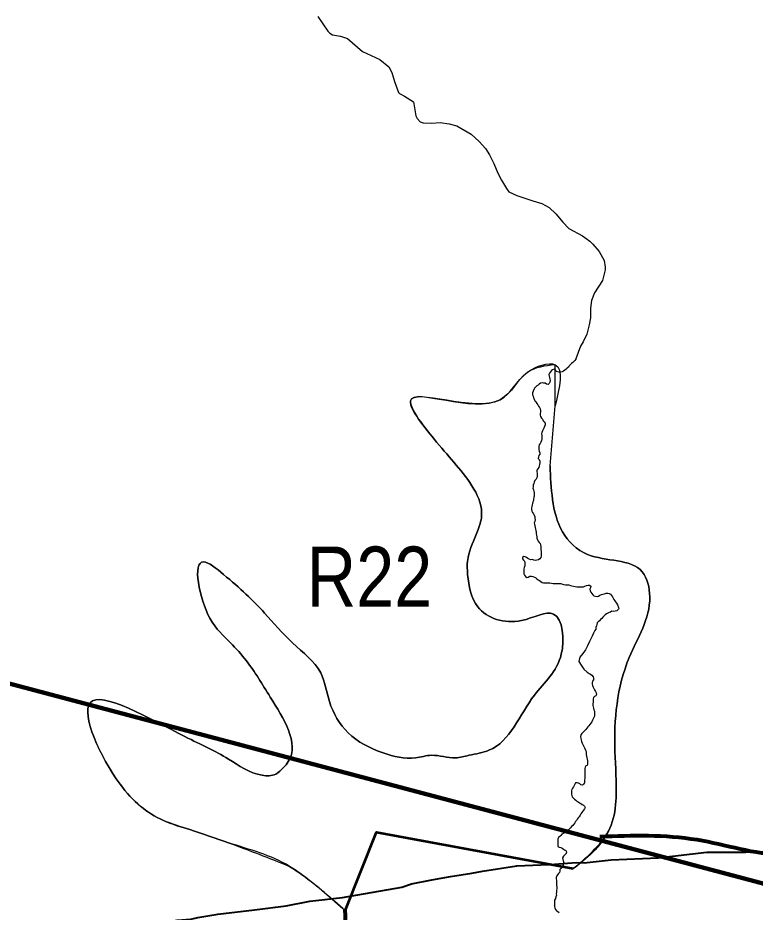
# Model space of a CAD drawing. Extents: x 553962 to 842807, y 8883888 to 9032388.
# Drawn here: x 729677 to 735808, y 8960680 to 8968113 of the extents above; entities that cross this region are included whole.
import ezdxf
from ezdxf.enums import TextEntityAlignment as Align

# ---------------------------------------------------------------- set-up
doc = ezdxf.new("R2010")
doc.units = 0
doc.header["$LTSCALE"] = 200
for name, color, linetype, lineweight in [('12', 7, 'Continuous', 25), ('24', 7, 'Continuous', 25), ('50', 7, 'Continuous', 80), ('51', 7, 'Continuous', 25), ('9', 7, 'Continuous', 90)]:
    doc.layers.add(name, color=color, linetype=linetype, lineweight=lineweight)
doc.layers.add('53', color=7, linetype='Continuous')

msp = doc.modelspace()

# ---------------------------------------------------------------- linework, layer by layer
at = {"layer": '12', "lineweight": 40}
for points in [[(735620.8, 8961178.7), (735731.5, 8961178.7), (735939.1, 8961184.7), (736086.4, 8961182.8), (736197.1, 8961189.1), (736304, 8961187.6), (736462.5, 8961200.2), (736543.4, 8961202.1), (736665.1, 8961195.8), (736768.2, 8961197.3), (737022.4, 8961176.7), (737121.8, 8961176.5), (737224.9, 8961184.4), (737328.1, 8961184.8), (737486.6, 8961197.6), (738285.5, 8961221)], [(734025.2, 8961072.3), (734102.4, 8961075.4), (734319.4, 8961091.8), (734386.9, 8961089), (734610.5, 8961116.1), (735000.8, 8961131.4), (735406.2, 8961178.8), (735620.8, 8961178.7)], [(733119.6, 8960947.4), (733273.3, 8960975.6), (733450.7, 8961003.1), (733541.8, 8961022), (733827, 8961064.4), (734025.2, 8961072.3)], [(731644.2, 8960700.6), (731907.1, 8960733.7), (732104.6, 8960770.6), (732375, 8960800.8), (732870.2, 8960888.2), (732949.7, 8960916.3), (733119.6, 8960947.4)], [(727488.2, 8960282.3), (728636.4, 8960199.6), (728903.4, 8960161.8), (729137.1, 8960189.3), (729219.7, 8960208.1), (729401, 8960258.8), (729465.4, 8960280.4), (729590.6, 8960330), (729719.4, 8960363), (729852.5, 8960406), (729969, 8960418.2), (730064.3, 8960434.8), (730362.8, 8960475.9), (730505.9, 8960510.9), (731000.5, 8960614.4), (731116.1, 8960622.6), (731172.1, 8960636.4), (731339.7, 8960662.3), (731644.2, 8960700.6)]]:
    msp.add_lwpolyline(points, dxfattribs=at)
at = {"layer": '24'}
for points in [[(732172.3, 8968124.3), (732254.1, 8968003.8), (732270.8, 8967986), (732292.3, 8967973.5), (732359.4, 8967962.3), (732419.1, 8967940.3), (732541.4, 8967832.4), (732686.6, 8967768.5), (732762.4, 8967705.5), (732787.2, 8967659.9), (732807.8, 8967584.8), (732842.4, 8967493.1), (732851.1, 8967484), (732892.3, 8967462.8), (732967.3, 8967414.9), (732986, 8967300), (732997.8, 8967278.1), (733022.8, 8967248.5), (733047.5, 8967241.4), (733120.3, 8967238.6), (733188.8, 8967243.5), (733264.7, 8967233.7), (733328, 8967214.7), (733447.7, 8967146.1), (733512.9, 8967086.8), (733564.5, 8967027.4), (733599.2, 8966975.3), (733599.2, 8966975.3), (733635.8, 8966903.5)], [(733635.8, 8966903.5), (733667.4, 8966823.6), (733697.2, 8966763.3), (733739, 8966694.9), (733760.7, 8966668.4), (733825.8, 8966637.8), (733959, 8966591.6), (734034.5, 8966569.7), (734094.6, 8966536.2), (734151.5, 8966485), (734209.2, 8966415.7), (734259.6, 8966363.7), (734370.9, 8966301.9), (734433.4, 8966256), (734458.6, 8966232.5), (734511.2, 8966171.1), (734552, 8966096.3), (734560.3, 8966041.1), (734559.6, 8966020.2), (734537.3, 8965930.7), (734471.1, 8965828), (734446.2, 8965764.4), (734439.5, 8965701), (734438, 8965620.3), (734427.4, 8965560.6), (734408.2, 8965484.4), (734379, 8965420.6), (734356.7, 8965384.2), (734317.4, 8965278.9)], [(734317.4, 8965278.9), (734316.7, 8965277.6), (734309.6, 8965266), (734300.3, 8965256.2), (734290.8, 8965248), (734280, 8965241.5), (734271, 8965232.4), (734262.1, 8965222.2), (734255.2, 8965210.8), (734246, 8965201.4), (734235.3, 8965192.4), (734225.2, 8965183.6), (734214.5, 8965176.8), (734203.3, 8965171.2), (734191.1, 8965169), (734176.5, 8965168.2), (734165.4, 8965170.5), (734153.3, 8965175.2), (734146.5, 8965187.1), (734135.5, 8965193.7), (734123.7, 8965189.1), (734113.9, 8965181), (734104.7, 8965171.5), (734096.9, 8965160.2), (734092, 8965148.5), (734093.8, 8965135.7), (734099.1, 8965124.2), (734101.8, 8965111.2), (734104.4, 8965098.9), (734101.7, 8965086.3), (734094.8, 8965075.1), (734085.3, 8965066.8), (734072.7, 8965069.6), (734061.6, 8965075.9), (734048.7, 8965077.6), (734035.9, 8965079.3), (734022.6, 8965077.8), (734012.9, 8965069.3), (734002.3, 8965061.6), (733992.1, 8965054.2), (733982.6, 8965044.5), (733973.5, 8965035.4), (733966.4, 8965023.8), (733961.2, 8965011.2), (733957.4, 8964996.8), (733956.8, 8964980.1), (733961.7, 8964967.6), (733965, 8964954.8), (733969.4, 8964942.7), (733975.5, 8964931.1), (733983, 8964920.4), (733992.3, 8964907.2), (733999.9, 8964896), (734007, 8964885.5), (734014.1, 8964874.7), (734019.1, 8964863.1), (734023, 8964850.6), (734021.8, 8964836.9), (734020.6, 8964824.1), (734020.5, 8964810.9), (734024.2, 8964798.7), (734031.2, 8964786.5), (734039.1, 8964776.3), (734045.8, 8964764.7), (734054.2, 8964754.9)], [(734054.2, 8964754.9), (734060.9, 8964743.3), (734062.1, 8964730.9), (734057.1, 8964716.4), (734051.1, 8964704.2), (734044.2, 8964692), (734039, 8964679.5), (734033.5, 8964667.7), (734031.7, 8964654.4), (734034.2, 8964641.1), (734034.2, 8964628.3), (734034.1, 8964613), (734031.7, 8964599), (734024.3, 8964586.6), (734018.8, 8964574.7), (734012.7, 8964563), (734010, 8964550.6), (734009.5, 8964537.9), (734009, 8964524.6), (734010.7, 8964510.9), (734016.3, 8964498.6), (734016.6, 8964486), (734010.2, 8964474.6), (734005, 8964463.3), (734003.8, 8964450.7), (734012.6, 8964441.7), (734016, 8964428.6), (734016.2, 8964415.1), (734015.3, 8964401.5), (734012.5, 8964389.2), (734008.2, 8964375), (733999.7, 8964365), (733992.6, 8964354.2), (733992.8, 8964341.2), (733995.2, 8964328.2), (733996.5, 8964315.3), (733996.1, 8964302.6)], [(733996.1, 8964302.6), (733991.3, 8964290.8), (733985.7, 8964278.4), (733977, 8964266.7), (733970.8, 8964254.3), (733966.8, 8964241.9), (733962.8, 8964229.6), (733960.8, 8964216.6), (733959.5, 8964204), (733963.7, 8964190.5), (733968, 8964177.9), (733970, 8964165.6), (733970.8, 8964152.7), (733969.3, 8964140.3), (733967.8, 8964127), (733965.9, 8964114.5), (733963.3, 8964101.8), (733960.2, 8964089.4), (733957.5, 8964076.7), (733954, 8964064.3), (733950.2, 8964052), (733949.4, 8964039.4), (733948.8, 8964026.1), (733950.4, 8964013.4), (733956.9, 8964002.4), (733964.9, 8963992.1), (733970.9, 8963980.8), (733975.1, 8963967.2), (733977.1, 8963954.1), (733977.3, 8963941.3), (733974.7, 8963928.5), (733969.8, 8963916.5), (733973.1, 8963904.2), (733975.6, 8963891), (733978.1, 8963878), (733980.9, 8963864.1), (733983.6, 8963851.7), (733985.7, 8963839), (733987.3, 8963825.2), (733990.2, 8963813), (733991.4, 8963800.2), (733993.4, 8963787.4), (733998.3, 8963775.9), (734004.5, 8963764.8), (734011.8, 8963753.8), (734019.7, 8963743.9), (734023.1, 8963731.8), (734024.4, 8963719), (734025.3, 8963704.3), (734026.4, 8963691.4), (734027.8, 8963677.9), (734028.3, 8963664.8), (734028.3, 8963651.9), (734028.2, 8963639.3), (734025.8, 8963627), (734017.3, 8963617.8), (734005.2, 8963608.5), (733993.3, 8963604.6), (733979.8, 8963604.3), (733967.2, 8963605.8), (733955.4, 8963610.6), (733942.5, 8963609.8), (733929.6, 8963614), (733918.5, 8963620.1), (733907.4, 8963627.1)], [(733907.4, 8963627.1), (733896, 8963632.6), (733883.9, 8963636.4), (733873.5, 8963629), (733873.4, 8963616.1), (733881.9, 8963606.8), (733890.4, 8963597.1), (733892.8, 8963584.5), (733892.8, 8963571.2), (733891.7, 8963557.6), (733888.4, 8963545.2), (733885.2, 8963532.5), (733883.4, 8963519.3), (733883.6, 8963506.2), (733884.6, 8963493.5), (733889.7, 8963481.7), (733897.6, 8963469.9), (733908.2, 8963462.6), (733921.2, 8963465.7), (733932.8, 8963471.8), (733947.2, 8963473.3), (733959.5, 8963471.2), (733971.9, 8963465.6), (733982.9, 8963458.6), (733993.4, 8963451), (734003.9, 8963442.6), (734014.3, 8963435.6), (734024.7, 8963427.4), (734036.2, 8963420), (734048.7, 8963417.4), (734061.5, 8963417), (734075.2, 8963416.7), (734088.5, 8963416.8), (734101.5, 8963418.1), (734115.2, 8963415.3), (734127.4, 8963412.7), (734140.3, 8963411.9)], [(734140.3, 8963411.9), (734153.1, 8963412.5), (734166.7, 8963413), (734179.8, 8963413), (734192.9, 8963411.4), (734204.7, 8963406.1), (734217.6, 8963403.3), (734230.9, 8963401.8), (734244.9, 8963401.4), (734258.5, 8963399.5), (734272.1, 8963396.5), (734284.7, 8963393.3), (734297.7, 8963389.8), (734310, 8963386.4), (734324.6, 8963384.7), (734339.7, 8963384.1), (734353.5, 8963383.7), (734366.6, 8963383.7), (734380.1, 8963384.7), (734392.7, 8963388.3), (734405.8, 8963393.8), (734418.5, 8963396.7), (734431.2, 8963396.6), (734441, 8963388.7), (734438.8, 8963376.4), (734433.9, 8963364.4), (734437.2, 8963351.6), (734442.7, 8963339.3), (734449.4, 8963327.7), (734457.2, 8963316.7), (734467.7, 8963309.5), (734480.4, 8963305.5), (734493.4, 8963305.1), (734506.2, 8963307.8), (734517.6, 8963314.2), (734529, 8963319.3), (734541.9, 8963323.9), (734554.4, 8963327), (734568.6, 8963330.6), (734581.7, 8963331.2), (734594.2, 8963329.3), (734605.3, 8963322.3), (734613.5, 8963312.8), (734620.4, 8963302.1), (734626.4, 8963290.9), (734633.3, 8963280.1), (734640, 8963269.1), (734647.3, 8963258.4), (734655.3, 8963248.2), (734662.7, 8963234.7), (734672.8, 8963211.7)], [(734672.8, 8963211.7), (734674.2, 8963206.7), (734674.2, 8963203.6), (734671.8, 8963197.4), (734666.7, 8963191.8), (734656.5, 8963184.6), (734644, 8963181), (734630.8, 8963180.4), (734617.4, 8963180.5), (734606.2, 8963174.5), (734593.3, 8963171.7), (734582, 8963165), (734571.1, 8963158.4), (734560.2, 8963150), (734550, 8963141.1), (734540.7, 8963132.2), (734531.7, 8963121.8), (734523.2, 8963111.8), (734513.7, 8963102.3), (734503.3, 8963094.3), (734495.2, 8963084.6), (734491.5, 8963070.7), (734487.3, 8963058.8), (734483.8, 8963046.6), (734481.8, 8963033.4), (734475.8, 8963021.3), (734469.1, 8963010), (734463.7, 8962997.9), (734452.3, 8962973.1)], [(734452.3, 8962973.1), (734447.6, 8962962.4), (734429.7, 8962928.5), (734414.2, 8962893.9), (734396.5, 8962860.8), (734373.9, 8962829.8), (734350.6, 8962800.1), (734340.4, 8962763.4), (734361.6, 8962732.1), (734382.8, 8962699.1), (734411.5, 8962673.7), (734426.3, 8962663.6), (734439.8, 8962657), (734450.1, 8962649.5), (734460.7, 8962637.1), (734463.7, 8962623.8), (734462.3, 8962611.2), (734455.9, 8962600), (734451.7, 8962588.5), (734451.6, 8962576.2), (734454.6, 8962563.8), (734460.7, 8962551.3), (734466, 8962539.4), (734473.2, 8962527.7), (734480.5, 8962515.1), (734485.3, 8962503.2), (734487.4, 8962490.2), (734483.7, 8962478.7), (734472.9, 8962472.5), (734463.9, 8962463.6), (734460.9, 8962451.8), (734460.9, 8962439.4), (734460.8, 8962426.2), (734458.8, 8962411.3), (734458.1, 8962398.5), (734460, 8962386.5), (734462.6, 8962374.7), (734466.6, 8962362.6), (734470.8, 8962350.7), (734471.7, 8962337.7), (734471.5, 8962322.5), (734471.3, 8962308.9), (734467.4, 8962297.2), (734460.8, 8962286.3), (734455.3, 8962275.4), (734448.8, 8962263.2), (734441, 8962251.4), (734433.2, 8962240.7), (734425.2, 8962229), (734417.4, 8962219.1), (734409.1, 8962209), (734400, 8962199.1), (734391.7, 8962190), (734383.7, 8962181), (734374.2, 8962173.1), (734366, 8962164.3), (734357.8, 8962153.6), (734354.8, 8962141), (734357.8, 8962124), (734360.1, 8962112), (734364.5, 8962097.4), (734370.5, 8962085.5), (734375.3, 8962073.5), (734380.1, 8962061.9), (734387.2, 8962050.9), (734392.9, 8962039.6), (734398.1, 8962027.3), (734401.7, 8962015.2), (734402.3, 8962002.2), (734402.4, 8961989.4), (734404.1, 8961976.6), (734406.8, 8961963.1), (734410.8, 8961952.5), (734414.1, 8961938.9), (734414.2, 8961925.2), (734413.8, 8961912.3), (734411.4, 8961900), (734399.9, 8961895.9), (734394.8, 8961885), (734391.5, 8961872.9), (734391.2, 8961870.4), (734391.1, 8961855.7), (734391, 8961841.3), (734390.9, 8961829.3), (734390.8, 8961816.6), (734390.7, 8961803.9), (734390.3, 8961791), (734390.1, 8961778.6), (734390, 8961766.5), (734388, 8961754.5), (734380.7, 8961744.3), (734371, 8961736.2), (734358.2, 8961738.1), (734350.1, 8961747.3), (734338.7, 8961752.7), (734327, 8961755.8), (734315.1, 8961754.3), (734307.7, 8961744), (734302.1, 8961733.4), (734296.4, 8961722.2), (734289.2, 8961711.3)], [(734289.2, 8961711.3), (734283.8, 8961700), (734281.5, 8961688.1), (734280.9, 8961674.6), (734280.8, 8961661.6), (734284.7, 8961649.7), (734287.4, 8961637.4), (734296.4, 8961627.5), (734306.7, 8961619), (734316.1, 8961610.8), (734326.2, 8961603.1), (734336, 8961596), (734346.8, 8961589.7), (734356.9, 8961582), (734368.8, 8961575.5), (734379.9, 8961568.9), (734388.6, 8961559.9), (734395.6, 8961549.8), (734388.5, 8961537.7), (734380.5, 8961527.4), (734372.8, 8961518.1), (734365.6, 8961507.4), (734359.4, 8961496), (734352.2, 8961485.5), (734344.5, 8961473.6), (734337.4, 8961463.9), (734328.9, 8961454.1), (734321.4, 8961443.2), (734315, 8961432.6), (734307.4, 8961421.2), (734299.3, 8961410.7), (734290.8, 8961400.6), (734280.7, 8961391.1), (734271.1, 8961380.8), (734263, 8961371.6), (734254, 8961362.1), (734243, 8961354.4), (734232.2, 8961347.1), (734222.1, 8961340.4), (734211.8, 8961333.8), (734201, 8961327), (734191.4, 8961318.2), (734182.9, 8961308.7), (734173.4, 8961301.1), (734167, 8961290.8), (734166.8, 8961278.6), (734166.7, 8961265.9), (734166.4, 8961252.4), (734165.8, 8961238.4), (734167.3, 8961226.5), (734178.3, 8961221.3), (734191, 8961218.2), (734202.9, 8961212.1), (734213, 8961204.5), (734223.8, 8961197.5), (734234.3, 8961191.3), (734239.4, 8961180.2), (734236.8, 8961167.9), (734227.7, 8961158.7), (734219.6, 8961150.8), (734213.2, 8961144.3), (734207.2, 8961131.5), (734207.9, 8961118.3), (734211.4, 8961106.2), (734218, 8961091.1)], [(734218, 8961091.1), (734207.8, 8961062.9), (734200, 8961053), (734190.9, 8961044.2), (734184.6, 8961033.6), (734182.6, 8961021.3), (734181.7, 8961009.3), (734171.8, 8961001.8), (734165.3, 8960991.3), (734157.6, 8960980.9), (734153.4, 8960969.1), (734153.9, 8960956.9), (734155.7, 8960944.8), (734155.6, 8960930.8), (734157.2, 8960918.6), (734157.3, 8960903.8), (734157.4, 8960891.6), (734158.6, 8960889.5), (734158.7, 8960875.6), (734155.4, 8960860.1), (734154.8, 8960846.8), (734154.5, 8960832.9), (734154.7, 8960820.1), (734151.4, 8960807.7), (734146.5, 8960794.6), (734140.1, 8960780.9), (734140, 8960767.8), (734139.7, 8960754.8), (734139.4, 8960740.2), (734140.4, 8960727.2), (734143.2, 8960714.9), (734147.9, 8960702.2), (734155.3, 8960690.7), (734166.3, 8960684.7), (734176.8, 8960677.5)]]:
    msp.add_lwpolyline(points, dxfattribs=at)
at = {"layer": '50'}
for points in [[(734517, 8961309.7), (735324.4, 8961282.7), (736033.5, 8961159), (736354.5, 8961171.9), (736656.3, 8961221), (736714.7, 8961372.7), (736765.2, 8961626.6), (736858.4, 8961762.2), (737019.8, 8961809.5), (737290.4, 8961808.3), (737499.7, 8961752.3), (737621.3, 8961810.7), (737698, 8961880.4), (737801.4, 8962031), (737987.9, 8962202.6)], [(728337.3, 8957392.9), (729070, 8957351.9), (729450.4, 8957327.7), (729981.6, 8957325.5), (730495.8, 8957696.2), (731342.6, 8958615.3), (731545.6, 8958733), (731838.9, 8958853.7), (732206, 8958911.4), (732387.3, 8958953.1), (732694.9, 8959037.8), (732806.5, 8959101.5), (732909.3, 8959451.2), (732717.7, 8959863.9), (732493.2, 8960149.8), (732419.1, 8960432.2), (732402.2, 8960575.4), (732399.6, 8960687.8), (732398.8, 8960707.8)]]:
    msp.add_spline(points, degree=3, dxfattribs=at)
at = {"layer": '51'}
for points in [[(734102.4, 8964390), (734143.9, 8964887.9), (734143.9, 8965230.1)], [(732399.4, 8960691.1), (732659.3, 8961345), (734295.2, 8961044.1), (734332.5, 8961071.2)]]:
    msp.add_lwpolyline(points, dxfattribs=at)
at = {"layer": '51', "lineweight": 53}
msp.add_lwpolyline([(732399.4, 8960691.1), (732659.3, 8961345), (734295.2, 8961044.1)], dxfattribs=at)
at = {"layer": '51'}
for points in [[(734143.9, 8965230.1), (733915.9, 8965167.9), (733687.8, 8964939.7), (732941.6, 8964929.4), (733159.2, 8964587.1), (733321.3, 8964396.2), (733532.7, 8963972.9), (733499.9, 8963846.1), (733420.1, 8963628.5), (733417, 8963485.7), (733501.3, 8963218.1), (733864, 8963104), (734131.7, 8963157.8), (734195.7, 8962823.9), (733971.8, 8962482.8), (733594.6, 8962025.3), (733428.7, 8961983.8), (733314.7, 8961963.1), (733117.8, 8961983.8), (732983, 8961963.1), (732713.5, 8962004.6), (732423.3, 8962170.5), (732267.8, 8962429.8), (732195.3, 8962668.4), (731961.3, 8962917.7), (731728.9, 8963166.2), (731386.8, 8963487.7), (731221, 8963591.4), (731274, 8963122.5), (731445.1, 8962919.5), (731577.2, 8962768.5), (731776.2, 8962467.8), (731925.8, 8961932), (731884.3, 8961880.1), (731822.1, 8961828.3), (731708.1, 8961817.9), (731428.3, 8961952.7), (731065.5, 8962139.4), (730277.8, 8962419.4), (730526.5, 8961745.3), (730887.1, 8961442.6), (731106, 8961366), (731429.4, 8961256.4), (731936.4, 8961060.9)], [(732399.4, 8960691.1), (732045.1, 8960986.9), (731936.4, 8961060.9), (731429.4, 8961256.4), (731106, 8961366), (730887.1, 8961442.6), (730526.5, 8961745.3), (730277.8, 8962419.4), (731065.5, 8962139.4), (731428.3, 8961952.7), (731708.1, 8961817.9), (731822.1, 8961828.3), (731884.3, 8961880.1), (731925.8, 8961932), (731776.2, 8962467.8), (731577.2, 8962768.5), (731445.1, 8962919.5), (731274, 8963122.5), (731221, 8963591.4), (731386.8, 8963487.7), (731728.9, 8963166.2), (731961.3, 8962917.7), (732195.3, 8962668.4), (732267.8, 8962429.8), (732423.3, 8962170.5), (732713.5, 8962004.6), (732983, 8961963.1), (733117.8, 8961983.8), (733314.7, 8961963.1), (733428.7, 8961983.8), (733594.6, 8962025.3), (733971.8, 8962482.8), (734195.7, 8962823.9), (734131.7, 8963157.8), (733864, 8963104), (733501.3, 8963218.1), (733417, 8963485.7), (733420.1, 8963628.5), (733499.9, 8963846.1), (733532.7, 8963972.9), (733321.3, 8964396.2), (733159.2, 8964587.1), (732941.6, 8964929.4), (733687.8, 8964939.7), (733915.9, 8965167.9), (734143.9, 8965230.1), (734143.9, 8964887.9)], [(734102.4, 8964390), (734123.2, 8964110), (734206.1, 8963840.3), (734413.4, 8963653.7), (734869.4, 8963508.5), (734931.6, 8963301), (734760.5, 8962796.1), (734641.4, 8962015), (734651.8, 8961631.2), (734610.3, 8961403), (734332.5, 8961071.2), (734291.7, 8961041.5)], [(734332.5, 8961071.2), (734610.3, 8961403), (734651.8, 8961631.2), (734641.4, 8962015), (734760.5, 8962796.1), (734931.6, 8963301), (734869.4, 8963508.5), (734413.4, 8963653.7), (734206.1, 8963840.3), (734123.2, 8964110), (734102.4, 8964390)], [(731936.4, 8961060.9), (732045.1, 8960986.9), (732399.4, 8960691.1)]]:
    msp.add_spline(points, degree=3, dxfattribs=at)
at = {"layer": '9'}
msp.add_line((738230.2, 8960292.9), (727062.8, 8963254.1), dxfattribs=at)

# ---------------------------------------------------------------- texts
at = {"layer": '53', "width": 0.85}
msp.add_text('R22', height=500, dxfattribs=at).set_placement((732601.2, 8963218.5), align=Align.CENTER)

doc.saveas('drawing.dxf')
